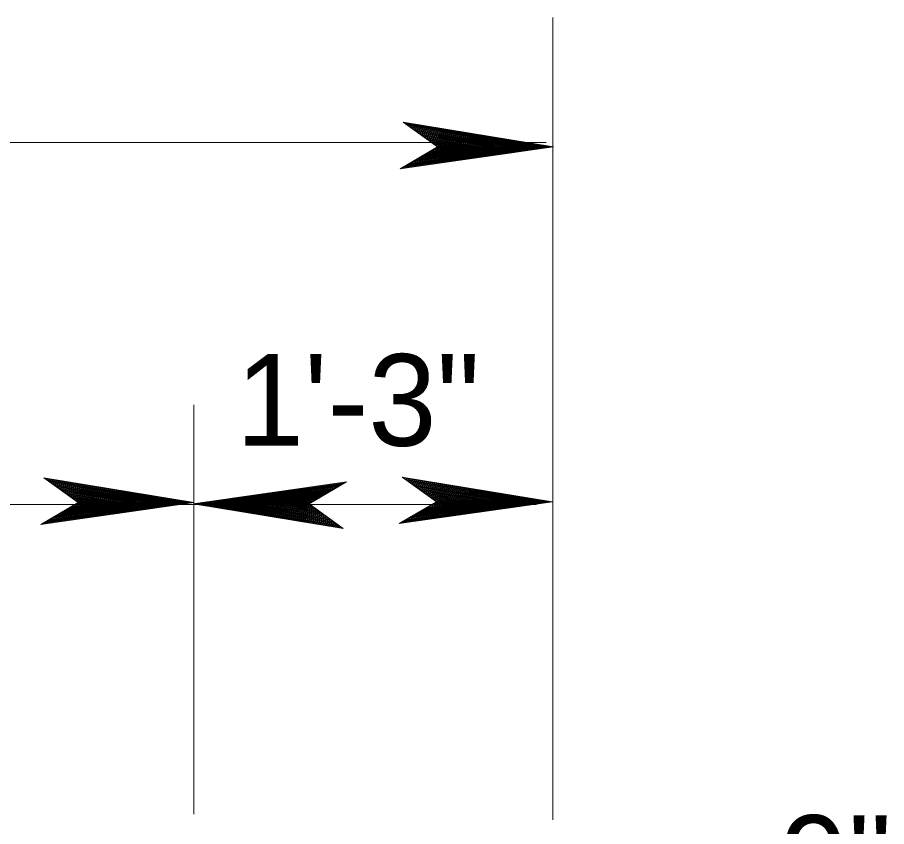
# Model space of a CAD drawing. Extents: x 144 to 252, y 360 to 425.
# Drawn here: x 178.382 to 181.492, y 402.487 to 405.383 of the extents above; entities that cross this region are included whole.
import ezdxf
from ezdxf.enums import TextEntityAlignment as Align

# ---------------------------------------------------------------- set-up
doc = ezdxf.new("R2010")
doc.units = 0
doc.header["$LTSCALE"] = 0.13
for name, color, linetype, lineweight in [('1', 7, 'Continuous', 40), ('16', 7, 'Continuous', 13), ('3', 7, 'Continuous', 13)]:
    doc.layers.add(name, color=color, linetype=linetype, lineweight=lineweight)

msp = doc.modelspace()

# ---------------------------------------------------------------- linework, layer by layer
at = {"layer": '1', "lineweight": 13}
for p, q in [((180.2978, 402.5724), (180.2978, 405.383)), ((180.2978, 402.5109), (180.2978, 402.6251))]:
    msp.add_line(p, q, dxfattribs=at)
at = {"layer": '3'}
for p, q in [((180.3001, 404.9192), (179.7624, 405.0084)), ((179.7624, 405.0084), (179.8849, 404.9193)), ((180.2857, 404.9198), (179.7657, 405.0061)), ((180.2748, 404.9198), (179.7689, 405.0037)), ((180.2604, 404.9198), (179.7732, 405.0006)), ((180.2477, 404.9198), (179.7769, 404.9979)), ((180.2363, 404.9198), (179.7802, 404.9955)), ((180.2219, 404.9198), (179.7845, 404.9923)), ((180.2092, 404.9198), (179.7883, 404.9896)), ((180.1954, 404.9198), (179.7923, 404.9867)), ((180.1816, 404.9198), (179.7964, 404.9837)), ((180.1683, 404.9198), (179.8003, 404.9808)), ((180.1544, 404.9198), (179.8044, 404.9778)), ((180.1418, 404.9198), (179.8082, 404.9752)), ((180.1304, 404.9198), (179.8116, 404.9727)), ((180.1147, 404.9198), (179.8162, 404.9693)), ((180.1009, 404.9198), (179.8202, 404.9663)), ((180.0829, 404.9203), (179.8245, 404.9632)), ((180.069, 404.9203), (179.8287, 404.9602)), ((156.2728, 404.9348), (180.2736, 404.9348)), ((180.0558, 404.9203), (179.8325, 404.9574)), ((180.0468, 404.9198), (179.8363, 404.9547)), ((180.0348, 404.9198), (179.8398, 404.9521)), ((180.0209, 404.9198), (179.8439, 404.9491)), ((180.0052, 404.9198), (179.8486, 404.9458)), ((179.9927, 404.9198), (179.8522, 404.9431)), ((179.9794, 404.9198), (179.8562, 404.9402)), ((179.9674, 404.9198), (179.8597, 404.9376)), ((179.9529, 404.9198), (179.864, 404.9346)), ((179.9391, 404.9198), (179.8682, 404.9316)), ((179.9264, 404.9198), (179.8718, 404.9288)), ((179.8849, 404.9193), (179.7513, 404.8414)), ((179.7513, 404.8414), (180.3001, 404.9192)), ((179.7573, 404.8449), (180.2857, 404.9198)), ((179.7608, 404.8469), (180.2748, 404.9198)), ((179.7654, 404.8496), (180.2604, 404.9198)), ((179.7695, 404.852), (180.2477, 404.9198)), ((179.7695, 404.852), (180.2477, 404.9198)), ((179.7732, 404.8542), (180.2363, 404.9198)), ((179.7777, 404.8568), (180.2219, 404.9198)), ((179.7818, 404.8592), (180.2092, 404.9198)), ((179.7862, 404.8617), (180.1954, 404.9198)), ((179.7907, 404.8643), (180.1816, 404.9198)), ((179.7949, 404.8668), (180.1683, 404.9198)), ((179.7994, 404.8695), (180.1544, 404.9198)), ((179.8034, 404.8717), (180.1418, 404.9198)), ((179.8072, 404.874), (180.1304, 404.9198)), ((179.8122, 404.8768), (180.1147, 404.9198)), ((179.8166, 404.8795), (180.1009, 404.9198)), ((179.8206, 404.8818), (180.0813, 404.9187)), ((179.8237, 404.8837), (180.0829, 404.9203)), ((179.8282, 404.8862), (180.069, 404.9203)), ((179.8324, 404.8887), (180.0558, 404.9203)), ((179.8339, 404.8896), (180.0468, 404.9198)), ((179.8378, 404.8918), (180.0348, 404.9198)), ((179.8423, 404.8945), (180.0209, 404.9198)), ((179.8473, 404.8973), (180.0052, 404.9198)), ((179.8513, 404.8997), (179.9927, 404.9198)), ((179.8556, 404.9022), (179.9794, 404.9198)), ((179.8594, 404.9045), (179.9674, 404.9198)), ((179.8641, 404.9072), (179.9529, 404.9198)), ((179.8685, 404.9097), (179.9391, 404.9198)), ((179.8726, 404.9121), (179.9264, 404.9198)), ((179.9132, 404.9198), (179.8757, 404.926)), ((179.8778, 404.9152), (179.9029, 404.9187)), ((179.9017, 404.9198), (179.8792, 404.9236)), ((179.8805, 404.9167), (179.9017, 404.9198)), ((179.8916, 404.9198), (179.8822, 404.9213)), ((179.8847, 404.9192), (180.3001, 404.9192)), ((179.0137, 403.4373), (179.0137, 403.9957)), ((180.2978, 403.4373), (180.2978, 403.9957)), ((179.0145, 403.6463), (178.4768, 403.7355)), ((178.4768, 403.7355), (178.5993, 403.6464)), ((179.0001, 403.6469), (178.4801, 403.7332)), ((178.9892, 403.6469), (178.4833, 403.7308)), ((178.9748, 403.6469), (178.4876, 403.7277)), ((178.9621, 403.6469), (178.4913, 403.725)), ((178.9507, 403.6469), (178.4947, 403.7226)), ((178.9363, 403.6469), (178.4989, 403.7194)), ((178.9236, 403.6469), (178.5027, 403.7167)), ((179.5593, 403.7201), (179.0106, 403.6423)), ((179.5533, 403.7166), (179.025, 403.6417)), ((179.4257, 403.6422), (179.5593, 403.7201)), ((180.2969, 403.6487), (179.7592, 403.7379)), ((179.7592, 403.7379), (179.8817, 403.6488)), ((180.2825, 403.6493), (179.7625, 403.7356)), ((180.2717, 403.6493), (179.7657, 403.7332)), ((180.2572, 403.6493), (179.77, 403.7301)), ((180.2445, 403.6493), (179.7738, 403.7274)), ((180.2332, 403.6493), (179.7771, 403.725)), ((180.2188, 403.6493), (179.7813, 403.7218)), ((180.206, 403.6493), (179.7851, 403.7191)), ((180.1923, 403.6493), (179.7892, 403.7162)), ((178.9098, 403.6469), (178.5067, 403.7138)), ((178.896, 403.6469), (178.5108, 403.7107)), ((178.8827, 403.6469), (178.5147, 403.7079)), ((178.8688, 403.6469), (178.5188, 403.7049)), ((178.8562, 403.6469), (178.5226, 403.7022)), ((178.8448, 403.6469), (178.526, 403.6997)), ((178.8292, 403.6469), (178.5306, 403.6964)), ((178.8153, 403.6469), (178.5347, 403.6934)), ((178.7973, 403.6474), (178.5389, 403.6903)), ((178.7834, 403.6474), (178.5431, 403.6873)), ((178.7703, 403.6474), (178.5469, 403.6845)), ((179.5498, 403.7146), (179.0358, 403.6417)), ((179.5452, 403.7119), (179.0503, 403.6417)), ((179.5412, 403.7095), (179.063, 403.6417)), ((179.5412, 403.7095), (179.063, 403.6417)), ((179.5375, 403.7073), (179.0743, 403.6417)), ((179.5329, 403.7047), (179.0888, 403.6417)), ((179.5288, 403.7022), (179.1015, 403.6417)), ((179.5244, 403.6997), (179.1153, 403.6417)), ((179.52, 403.6972), (179.1291, 403.6417)), ((179.5157, 403.6947), (179.1423, 403.6417)), ((179.5112, 403.692), (179.1562, 403.6417)), ((179.5072, 403.6898), (179.1688, 403.6417)), ((179.5035, 403.6875), (179.1803, 403.6417)), ((179.4985, 403.6847), (179.1959, 403.6417)), ((180.1784, 403.6493), (179.7933, 403.7132)), ((180.1652, 403.6493), (179.7972, 403.7103)), ((180.1513, 403.6493), (179.8012, 403.7073)), ((180.1387, 403.6493), (179.805, 403.7047)), ((180.1273, 403.6493), (179.8084, 403.7022)), ((180.1116, 403.6493), (179.813, 403.6988)), ((180.0977, 403.6493), (179.8171, 403.6958)), ((180.0797, 403.6498), (179.8213, 403.6927)), ((180.0658, 403.6498), (179.8255, 403.6898)), ((180.0527, 403.6498), (179.8293, 403.6869)), ((180.0436, 403.6493), (179.8331, 403.6842)), ((178.7612, 403.6469), (178.5507, 403.6817)), ((178.7492, 403.6469), (178.5542, 403.6792)), ((178.7353, 403.6469), (178.5583, 403.6762)), ((178.7197, 403.6469), (178.563, 403.6729)), ((178.7071, 403.6469), (178.5667, 403.6702)), ((178.6938, 403.6469), (178.5706, 403.6673)), ((178.6818, 403.6469), (178.5742, 403.6647)), ((178.6673, 403.6469), (178.5784, 403.6617)), ((178.6535, 403.6469), (178.5826, 403.6587)), ((178.6408, 403.6469), (178.5863, 403.6559)), ((178.6276, 403.6469), (178.5902, 403.6531)), ((179.4941, 403.682), (179.2097, 403.6417)), ((179.4869, 403.6778), (179.2277, 403.6412)), ((179.4901, 403.6798), (179.2293, 403.6427)), ((179.4825, 403.6753), (179.2417, 403.6412)), ((179.4783, 403.6728), (179.2548, 403.6412)), ((179.4767, 403.6719), (179.2639, 403.6417)), ((179.4728, 403.6697), (179.2759, 403.6417)), ((179.4684, 403.667), (179.2897, 403.6417)), ((179.4634, 403.6642), (179.3054, 403.6417)), ((179.4593, 403.6617), (179.318, 403.6417)), ((179.4551, 403.6592), (179.3312, 403.6417)), ((179.4512, 403.657), (179.3432, 403.6417)), ((179.4466, 403.6543), (179.3577, 403.6417)), ((180.0316, 403.6493), (179.8367, 403.6816)), ((180.0178, 403.6493), (179.8407, 403.6786)), ((180.0021, 403.6493), (179.8454, 403.6753)), ((179.9895, 403.6493), (179.8491, 403.6726)), ((179.9762, 403.6493), (179.853, 403.6697)), ((179.9642, 403.6493), (179.8566, 403.6671)), ((179.9497, 403.6493), (179.8608, 403.6641)), ((179.9359, 403.6493), (179.865, 403.6611)), ((179.9232, 403.6493), (179.8687, 403.6583)), ((179.91, 403.6493), (179.8726, 403.6555)), ((179.8986, 403.6493), (179.876, 403.6531)), ((156.2738, 403.6397), (178.9784, 403.6397)), ((178.5993, 403.6464), (178.4657, 403.5685)), ((178.4657, 403.5685), (179.0145, 403.6463)), ((178.4717, 403.572), (179.0001, 403.6469)), ((178.4752, 403.574), (178.9892, 403.6469)), ((178.4798, 403.5767), (178.9748, 403.6469)), ((178.4839, 403.5791), (178.9621, 403.6469)), ((178.4839, 403.5791), (178.9621, 403.6469)), ((178.4876, 403.5813), (178.9507, 403.6469)), ((178.4922, 403.5839), (178.9363, 403.6469)), ((178.4963, 403.5863), (178.9236, 403.6469)), ((178.5007, 403.5888), (178.9098, 403.6469)), ((178.5051, 403.5914), (178.896, 403.6469)), ((178.5093, 403.5939), (178.8827, 403.6469)), ((178.5138, 403.5966), (178.8688, 403.6469)), ((178.5178, 403.5988), (178.8562, 403.6469)), ((178.5216, 403.6011), (178.8448, 403.6469)), ((178.5266, 403.6039), (178.8292, 403.6469)), ((178.531, 403.6066), (178.8153, 403.6469)), ((178.535, 403.6088), (178.7957, 403.6458)), ((178.5382, 403.6107), (178.7973, 403.6474)), ((178.5426, 403.6133), (178.7834, 403.6474)), ((178.5468, 403.6158), (178.7703, 403.6474)), ((178.5483, 403.6167), (178.7612, 403.6469)), ((178.5522, 403.6189), (178.7492, 403.6469)), ((178.5567, 403.6216), (178.7353, 403.6469)), ((178.5617, 403.6244), (178.7197, 403.6469)), ((178.5657, 403.6268), (178.7071, 403.6469)), ((178.57, 403.6293), (178.6938, 403.6469)), ((178.5738, 403.6316), (178.6818, 403.6469)), ((178.5785, 403.6343), (178.6673, 403.6469)), ((178.5829, 403.6368), (178.6535, 403.6469)), ((178.587, 403.6392), (178.6408, 403.6469)), ((178.5923, 403.6422), (178.6173, 403.6458)), ((178.6162, 403.6469), (178.5936, 403.6507)), ((178.5949, 403.6438), (178.6162, 403.6469)), ((178.606, 403.6469), (178.5966, 403.6484)), ((178.5991, 403.6463), (179.0145, 403.6463)), ((180.2397, 403.6397), (178.9784, 403.6397)), ((179.0106, 403.6423), (179.5482, 403.5531)), ((179.426, 403.6423), (179.0106, 403.6423)), ((179.025, 403.6417), (179.545, 403.5554)), ((179.0358, 403.6417), (179.5418, 403.5577)), ((179.0503, 403.6417), (179.5375, 403.5609)), ((179.063, 403.6417), (179.5337, 403.5636)), ((179.0743, 403.6417), (179.5304, 403.566)), ((179.0888, 403.6417), (179.5262, 403.5692)), ((179.1015, 403.6417), (179.5224, 403.5719)), ((179.1153, 403.6417), (179.5183, 403.5748)), ((179.1291, 403.6417), (179.5143, 403.5778)), ((179.1423, 403.6417), (179.5103, 403.5807)), ((179.1562, 403.6417), (179.5062, 403.5837)), ((179.1688, 403.6417), (179.5025, 403.5863)), ((179.1803, 403.6417), (179.4991, 403.5888)), ((179.1959, 403.6417), (179.4945, 403.5922)), ((179.2097, 403.6417), (179.4904, 403.5952)), ((179.2277, 403.6412), (179.4862, 403.5983)), ((179.2417, 403.6412), (179.482, 403.6012)), ((179.2548, 403.6412), (179.4782, 403.6041)), ((179.2639, 403.6417), (179.4744, 403.6068)), ((179.2759, 403.6417), (179.4708, 403.6094)), ((179.2897, 403.6417), (179.4667, 403.6124)), ((179.3054, 403.6417), (179.4621, 403.6157)), ((179.318, 403.6417), (179.4584, 403.6184)), ((179.3312, 403.6417), (179.4545, 403.6212)), ((179.3432, 403.6417), (179.4509, 403.6239)), ((179.3577, 403.6417), (179.4467, 403.6269)), ((179.4422, 403.6517), (179.3716, 403.6417)), ((179.3716, 403.6417), (179.4425, 403.6299)), ((179.4381, 403.6494), (179.3842, 403.6417)), ((179.3842, 403.6417), (179.4388, 403.6327)), ((179.3975, 403.6417), (179.4349, 403.6355)), ((179.4328, 403.6463), (179.4077, 403.6427)), ((179.4302, 403.6447), (179.4089, 403.6417)), ((179.4089, 403.6417), (179.4315, 403.6379)), ((179.4191, 403.6417), (179.4285, 403.6402)), ((179.5482, 403.5531), (179.4257, 403.6422)), ((179.8817, 403.6488), (179.7482, 403.5709)), ((179.7482, 403.5709), (180.2969, 403.6487)), ((179.7542, 403.5744), (180.2825, 403.6493)), ((179.7577, 403.5764), (180.2717, 403.6493)), ((179.7622, 403.5791), (180.2572, 403.6493)), ((179.7663, 403.5815), (180.2445, 403.6493)), ((179.7663, 403.5815), (180.2445, 403.6493)), ((179.77, 403.5837), (180.2332, 403.6493)), ((179.7746, 403.5863), (180.2188, 403.6493)), ((179.7787, 403.5888), (180.206, 403.6493)), ((179.7831, 403.5913), (180.1923, 403.6493)), ((179.7875, 403.5938), (180.1784, 403.6493)), ((179.7918, 403.5963), (180.1652, 403.6493)), ((179.7962, 403.599), (180.1513, 403.6493)), ((179.8003, 403.6012), (180.1387, 403.6493)), ((179.804, 403.6035), (180.1273, 403.6493)), ((179.809, 403.6063), (180.1116, 403.6493)), ((179.8134, 403.609), (180.0977, 403.6493)), ((179.8174, 403.6112), (180.0782, 403.6482)), ((179.8206, 403.6132), (180.0797, 403.6498)), ((179.825, 403.6157), (180.0658, 403.6498)), ((179.8293, 403.6182), (180.0527, 403.6498)), ((179.8307, 403.6191), (180.0436, 403.6493)), ((179.8347, 403.6213), (180.0316, 403.6493)), ((179.8391, 403.624), (180.0178, 403.6493)), ((179.8441, 403.6268), (180.0021, 403.6493)), ((179.8482, 403.6293), (179.9895, 403.6493)), ((179.8524, 403.6318), (179.9762, 403.6493)), ((179.8562, 403.634), (179.9642, 403.6493)), ((179.8609, 403.6367), (179.9497, 403.6493)), ((179.8653, 403.6393), (179.9359, 403.6493)), ((179.8694, 403.6416), (179.9232, 403.6493)), ((179.8747, 403.6447), (179.8997, 403.6482)), ((179.8773, 403.6463), (179.8986, 403.6493)), ((179.8884, 403.6493), (179.879, 403.6508)), ((179.8815, 403.6487), (180.2969, 403.6487)), ((179.0137, 403.4373), (179.0137, 403.5913)), ((179.0137, 403.3788), (179.0137, 403.5417)), ((179.0137, 402.5312), (179.0137, 403.5417)), ((180.2978, 402.5231), (180.2978, 402.6251))]:
    msp.add_line(p, q, dxfattribs=at)

# ---------------------------------------------------------------- texts
at = {"layer": '16'}
msp.add_text('1\'-3"', height=0.3281, dxfattribs=at).set_placement((179.6008, 403.8496), align=Align.CENTER)
msp.add_text('9"', height=0.3281, dxfattribs=at).set_placement((181.1109, 402.1992))

doc.saveas('drawing.dxf')
